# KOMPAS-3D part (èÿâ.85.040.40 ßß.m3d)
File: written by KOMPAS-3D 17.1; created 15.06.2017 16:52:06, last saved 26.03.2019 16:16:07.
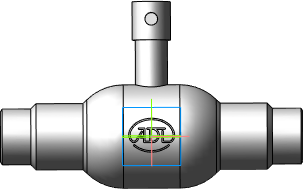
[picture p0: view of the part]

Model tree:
1. Операция без истории:2  (labels: Сталь 20  ГОСТ 1050-88)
